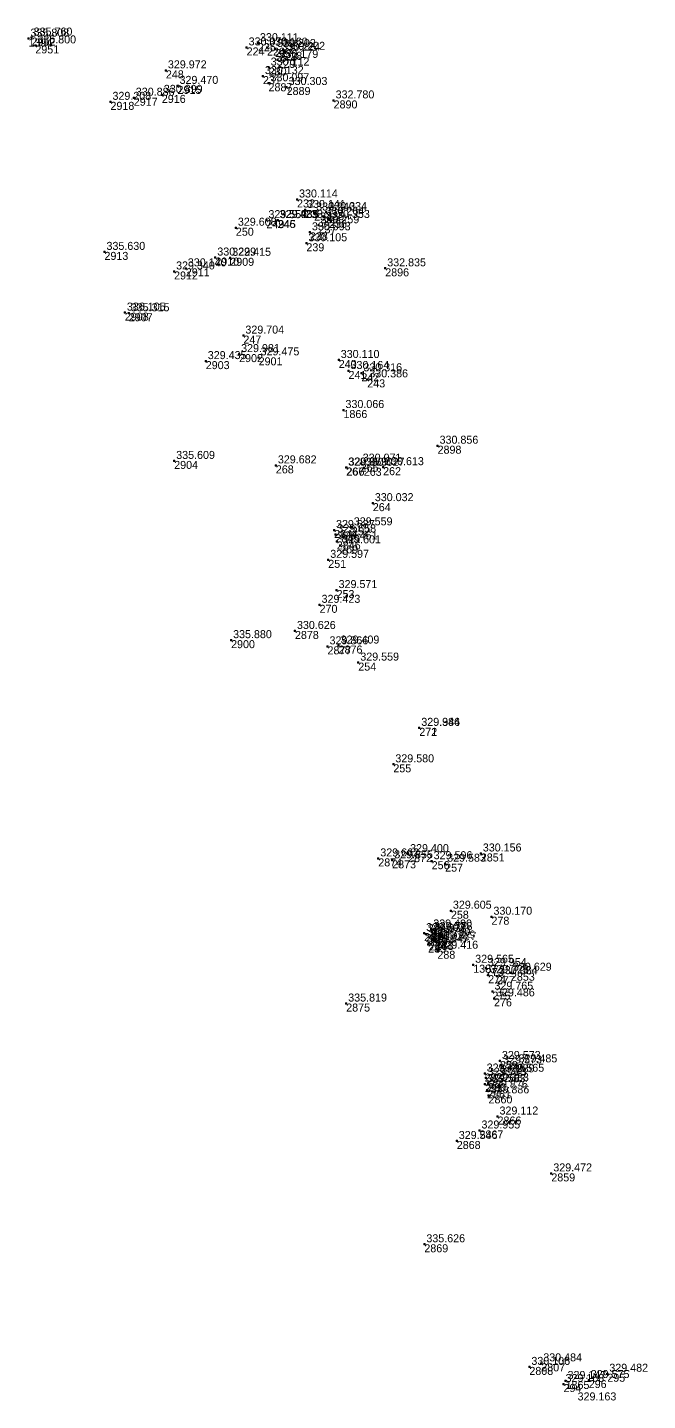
# Model space of a CAD drawing. Extents: x -829398 to -819400, y -1074439 to -1067977.
# Drawn here: x -822787.3 to -822694.5, y -1071096.4 to -1070890.5 of the extents above; entities that cross this region are included whole.
import ezdxf

# ---------------------------------------------------------------- set-up
doc = ezdxf.new("R2010")
doc.units = 0
for name, color, linetype in [('Vrstva 60', 7, 'Continuous'), ('Vrstva 61', 7, 'Continuous'), ('Čísla bodů_doměření_2012', 7, 'Continuous')]:
    doc.layers.add(name, color=color, linetype=linetype)

# ---------------------------------------------------------------- blocks, each defined once
blk = doc.blocks.new('BOD')
at = {"layer": 'Čísla bodů_doměření_2012'}
for p, q in [((-0.15, 0), (0.15, 0)), ((0, -0.15), (0, 0.15))]:
    blk.add_line(p, q, dxfattribs=at)

msp = doc.modelspace()

# ---------------------------------------------------------------- block references
at = {"layer": 'Vrstva 60'}
for p in [(-822787.193, -1070892.156), (-822786.72, -1070892.001), (-822786.165, -1070893.173), (-822752.813, -1070892.84), (-822754.514, -1070893.474), (-822751.46, -1070893.505), (-822750.245, -1070893.708), (-822749.594, -1070894.267), (-822748.866, -1070894.137), (-822766.606, -1070896.916), (-822751.202, -1070896.494), (-822749.889, -1070895.353), (-822764.862, -1070899.241), (-822752.07, -1070897.773), (-822751.234, -1070898.85), (-822771.414, -1070901.018), (-822767.216, -1070900.59), (-822748.517, -1070899.413), (-822741.481, -1070901.421), (-822774.91, -1070901.634), (-822746.959, -1070916.274), (-822745.758, -1070917.843), (-822751.548, -1070919.376), (-822749.879, -1070919.354), (-822749.826, -1070919.357), (-822744.397, -1070918.233), (-822742.979, -1070918.869), (-822742.576, -1070918.166), (-822742.161, -1070919.339), (-822756.124, -1070920.509), (-822745.035, -1070921.196), (-822743.74, -1070920.14), (-822745.557, -1070922.838), (-822775.808, -1070924.132), (-822759.202, -1070924.98), (-822756.96, -1070925.02), (-822765.381, -1070927.065), (-822763.621, -1070926.6), (-822733.747, -1070926.597), (-822772.751, -1070933.233), (-822772.168, -1070933.336), (-822754.997, -1070936.683), (-822760.633, -1070940.507), (-822755.638, -1070939.456), (-822752.715, -1070939.944), (-822740.712, -1070940.338), (-822739.247, -1070941.986), (-822737.323, -1070942.336), (-822736.436, -1070943.248), (-822740.003, -1070947.844), (-822725.905, -1070953.193), (-822765.363, -1070955.474), (-822750.134, -1070956.141), (-822739.603, -1070956.467), (-822739.539, -1070956.468), (-822737.423, -1070955.877), (-822736.965, -1070956.506), (-822734.064, -1070956.41), (-822735.609, -1070961.805), (-822741.421, -1070965.832), (-822741.217, -1070966.486), (-822738.758, -1070965.43), (-822740.999, -1070967.538), (-822740.489, -1070968.134), (-822742.283, -1070970.303), (-822741.033, -1070974.837), (-822743.582, -1070977.048), (-822747.272, -1070980.967), (-822756.839, -1070982.346), (-822742.392, -1070983.277), (-822740.731, -1070983.155), (-822737.784, -1070985.714), (-822728.645, -1070995.491), (-822728.643, -1070995.503), (-822732.532, -1071000.963), (-822730.321, -1071014.431), (-822719.428, -1071014.33), (-822734.788, -1071015.067), (-822732.707, -1071015.355), (-822726.792, -1071015.487), (-822724.771, -1071015.862), (-822723.908, -1071022.91), (-822717.833, -1071023.813), (-822727.922, -1071026.272), (-822727.675, -1071026.427), (-822727.094, -1071026.949), (-822726.85, -1071025.725), (-822726.781, -1071026.1), (-822727.32, -1071027.979), (-822727.221, -1071027.675), (-822726.327, -1071027.38), (-822726.196, -1071027.586), (-822725.933, -1071028.911), (-822720.57, -1071031.015), (-822718.657, -1071031.513), (-822718.324, -1071032.581), (-822717.021, -1071032.727), (-822714.914, -1071032.21), (-822717.686, -1071035.047), (-822739.592, -1071036.83), (-822717.449, -1071036.049), (-822716.567, -1071045.441), (-822718.85, -1071047.324), (-822716.381, -1071046.107), (-822716.032, -1071047.356), (-822714.071, -1071045.95), (-822718.819, -1071048.912), (-822718.665, -1071047.946), (-822718.334, -1071048.77), (-822718.491, -1071049.827), (-822718.272, -1071050.598), (-822716.924, -1071053.77), (-822723.03, -1071057.437), (-822719.631, -1071055.863), (-822708.868, -1071062.296), (-822727.886, -1071072.923), (-822710.368, -1071090.775), (-822712.153, -1071091.309), (-822700.475, -1071092.335), (-822707.035, -1071093.882), (-822706.732, -1071093.418), (-822703.263, -1071093.281)]:
    msp.add_blockref('BOD', p, dxfattribs=at)

# ---------------------------------------------------------------- texts
for s, p in [('1394', (-822787.193, -1070893.356)), ('2952', (-822786.72, -1070893.201)), ('225', (-822752.813, -1070894.04)), ('2951', (-822786.165, -1070894.373)), ('224', (-822754.514, -1070894.674)), ('226', (-822751.46, -1070894.705)), ('227', (-822750.245, -1070894.908)), ('223', (-822749.594, -1070895.467)), ('228', (-822748.866, -1070895.337)), ('248', (-822766.606, -1070898.116)), ('230', (-822751.202, -1070897.694)), ('229', (-822749.889, -1070896.553)), ('2915', (-822764.862, -1070900.441)), ('231', (-822752.07, -1070898.973)), ('2887', (-822751.234, -1070900.05)), ('2917', (-822771.414, -1070902.218)), ('2916', (-822767.216, -1070901.79)), ('2889', (-822748.517, -1070900.613)), ('2918', (-822774.91, -1070902.834)), ('2890', (-822741.481, -1070902.621)), ('232', (-822746.959, -1070917.474)), ('249', (-822751.548, -1070920.576)), ('246', (-822749.879, -1070920.554)), ('245', (-822749.826, -1070920.557)), ('233', (-822745.758, -1070919.043)), ('234', (-822744.397, -1070919.433)), ('244', (-822742.979, -1070920.069)), ('235', (-822742.576, -1070919.366)), ('236', (-822742.161, -1070920.539)), ('250', (-822756.124, -1070921.709)), ('238', (-822745.035, -1070922.396)), ('237', (-822743.74, -1070921.34)), ('239', (-822745.557, -1070924.038)), ('2913', (-822775.808, -1070925.332)), ('2910', (-822759.202, -1070926.18)), ('2909', (-822756.96, -1070926.22)), ('2912', (-822765.381, -1070928.265)), ('2911', (-822763.621, -1070927.8)), ('2896', (-822733.747, -1070927.797)), ('2908', (-822772.751, -1070934.433)), ('2907', (-822772.168, -1070934.536)), ('247', (-822754.997, -1070937.883)), ('2902', (-822755.638, -1070940.656)), ('2901', (-822752.715, -1070941.144)), ('240', (-822740.712, -1070941.538)), ('2903', (-822760.633, -1070941.707)), ('241', (-822739.247, -1070943.186)), ('242', (-822737.323, -1070943.536)), ('243', (-822736.436, -1070944.448)), ('1866', (-822740.003, -1070949.044)), ('2898', (-822725.905, -1070954.393)), ('2904', (-822765.363, -1070956.674)), ('268', (-822750.134, -1070957.341)), ('267', (-822739.603, -1070957.667)), ('266', (-822739.539, -1070957.668)), ('265', (-822737.423, -1070957.077)), ('263', (-822736.965, -1070957.706)), ('262', (-822734.064, -1070957.61)), ('264', (-822735.609, -1070963.005)), ('2844', (-822741.421, -1070967.032)), ('2845', (-822741.217, -1070967.686)), ('252', (-822738.758, -1070966.63)), ('2846', (-822740.999, -1070968.738)), ('269', (-822740.489, -1070969.334)), ('251', (-822742.283, -1070971.503)), ('253', (-822741.033, -1070976.037)), ('270', (-822743.582, -1070978.248)), ('2878', (-822747.272, -1070982.167)), ('2900', (-822756.839, -1070983.546)), ('2877', (-822742.392, -1070984.477)), ('2876', (-822740.731, -1070984.355)), ('254', (-822737.784, -1070986.914)), ('271', (-822728.645, -1070996.691)), ('272', (-822728.643, -1070996.703)), ('255', (-822732.532, -1071002.163)), ('2872', (-822730.321, -1071015.631)), ('2851', (-822719.428, -1071015.53)), ('2874', (-822734.788, -1071016.267)), ('2873', (-822732.707, -1071016.555)), ('256', (-822726.792, -1071016.687)), ('257', (-822724.771, -1071017.062)), ('258', (-822723.908, -1071024.11)), ('278', (-822717.833, -1071025.013)), ('287', (-822727.922, -1071027.472)), ('286', (-822727.675, -1071027.627)), ('281', (-822726.85, -1071026.925)), ('280', (-822726.781, -1071027.3)), ('285', (-822727.32, -1071029.179)), ('284', (-822727.221, -1071028.875)), ('279', (-822727.094, -1071028.149)), ('282', (-822726.327, -1071028.58)), ('283', (-822726.196, -1071028.786)), ('288', (-822725.933, -1071030.111)), ('1387', (-822720.57, -1071032.215)), ('273', (-822718.657, -1071032.713)), ('274', (-822718.324, -1071033.781)), ('277', (-822717.021, -1071033.927)), ('2853', (-822714.914, -1071033.41)), ('275', (-822717.686, -1071036.247)), ('2875', (-822739.592, -1071038.03)), ('276', (-822717.449, -1071037.249)), ('293', (-822718.85, -1071048.524)), ('259', (-822716.567, -1071046.641)), ('260', (-822716.381, -1071047.307)), ('261', (-822716.032, -1071048.556)), ('289', (-822714.071, -1071047.15)), ('291', (-822718.819, -1071050.112)), ('292', (-822718.665, -1071049.146)), ('290', (-822718.334, -1071049.97)), ('2861', (-822718.491, -1071051.027)), ('2860', (-822718.272, -1071051.798)), ('2866', (-822716.924, -1071054.97)), ('2868', (-822723.03, -1071058.637)), ('2867', (-822719.631, -1071057.063)), ('2859', (-822708.868, -1071063.496)), ('2869', (-822727.886, -1071074.123)), ('2808', (-822712.153, -1071092.509)), ('2807', (-822710.368, -1071091.975)), ('295', (-822700.475, -1071093.535)), ('294', (-822707.035, -1071095.082)), ('1865', (-822706.732, -1071094.618)), ('296', (-822703.263, -1071094.481))]:
    msp.add_text(s, height=1.2, dxfattribs=at).set_placement(p)
at = {"layer": 'Vrstva 61'}
for s, p in [('335.808', (-822786.893, -1070891.856)), ('335.760', (-822786.42, -1070891.701)), ('335.800', (-822785.865, -1070892.873)), ('330.070', (-822754.214, -1070893.174)), ('330.111', (-822752.513, -1070892.54)), ('330.160', (-822751.16, -1070893.205)), ('330.202', (-822749.945, -1070893.408)), ('330.224', (-822749.294, -1070893.967)), ('330.202', (-822748.566, -1070893.837)), ('330.112', (-822750.902, -1070896.194)), ('330.179', (-822749.589, -1070895.053)), ('329.972', (-822766.306, -1070896.616)), ('330.132', (-822751.77, -1070897.473)), ('330.899', (-822766.916, -1070900.29)), ('329.470', (-822764.562, -1070898.941)), ('330.097', (-822750.934, -1070898.55)), ('330.303', (-822748.217, -1070899.113)), ('329.208', (-822774.61, -1070901.334)), ('330.886', (-822771.114, -1070900.718)), ('332.780', (-822741.181, -1070901.121)), ('330.114', (-822746.659, -1070915.974)), ('330.141', (-822745.458, -1070917.543)), ('330.240', (-822744.097, -1070917.933)), ('330.264', (-822742.679, -1070918.569)), ('330.334', (-822742.276, -1070917.866)), ('329.608', (-822755.824, -1070920.209)), ('329.551', (-822751.248, -1070919.076)), ('329.489', (-822749.579, -1070919.054)), ('329.935', (-822749.526, -1070919.057)), ('330.093', (-822744.735, -1070920.896)), ('330.259', (-822743.44, -1070919.84)), ('330.353', (-822741.861, -1070919.039)), ('330.105', (-822745.257, -1070922.538)), ('335.630', (-822775.508, -1070923.832)), ('330.229', (-822758.902, -1070924.68)), ('329.415', (-822756.66, -1070924.72)), ('329.340', (-822765.081, -1070926.765)), ('330.140', (-822763.321, -1070926.3)), ('332.835', (-822733.447, -1070926.297)), ('336.105', (-822772.451, -1070932.933)), ('335.315', (-822771.868, -1070933.036)), ('329.704', (-822754.697, -1070936.383)), ('329.981', (-822755.338, -1070939.156)), ('329.435', (-822760.333, -1070940.207)), ('329.475', (-822752.415, -1070939.644)), ('330.110', (-822740.412, -1070940.038)), ('330.164', (-822738.947, -1070941.686)), ('330.316', (-822737.023, -1070942.036)), ('330.386', (-822736.136, -1070942.948)), ('330.066', (-822739.703, -1070947.544)), ('330.856', (-822725.605, -1070952.893)), ('335.609', (-822765.063, -1070955.174)), ('329.682', (-822749.834, -1070955.841)), ('330.071', (-822737.123, -1070955.577)), ('329.379', (-822739.303, -1070956.167)), ('329.953', (-822739.239, -1070956.168)), ('330.027', (-822736.665, -1070956.206)), ('330.613', (-822733.764, -1070956.11)), ('330.032', (-822735.309, -1070961.505)), ('329.687', (-822741.121, -1070965.532)), ('329.658', (-822740.917, -1070966.186)), ('329.559', (-822738.458, -1070965.13)), ('329.461', (-822740.699, -1070967.238)), ('329.601', (-822740.189, -1070967.834)), ('329.597', (-822741.983, -1070970.003)), ('329.571', (-822740.733, -1070974.537)), ('329.423', (-822743.282, -1070976.748)), ('330.626', (-822746.972, -1070980.667)), ('335.880', (-822756.539, -1070982.046)), ('329.866', (-822742.092, -1070982.977)), ('329.409', (-822740.431, -1070982.855)), ('329.559', (-822737.484, -1070985.414)), ('329.946', (-822728.345, -1070995.191)), ('329.384', (-822728.343, -1070995.203)), ('329.580', (-822732.232, -1071000.663)), ('329.662', (-822734.488, -1071014.767)), ('329.855', (-822732.407, -1071015.055)), ('329.400', (-822730.021, -1071014.131)), ('329.596', (-822726.492, -1071015.187)), ('329.583', (-822724.471, -1071015.562)), ('330.156', (-822719.128, -1071014.03)), ('329.605', (-822723.608, -1071022.61)), ('330.170', (-822717.533, -1071023.513)), ('329.603', (-822727.622, -1071025.972)), ('329.490', (-822726.55, -1071025.425)), ('329.778', (-822726.481, -1071025.8)), ('329.938', (-822727.375, -1071026.127)), ('329.647', (-822727.02, -1071027.679)), ('329.936', (-822726.921, -1071027.375)), ('329.790', (-822726.794, -1071026.649)), ('329.759', (-822726.027, -1071027.08)), ('329.547', (-822725.896, -1071027.286)), ('329.416', (-822725.633, -1071028.611)), ('329.565', (-822720.27, -1071030.715)), ('329.954', (-822718.357, -1071031.213)), ('330.629', (-822714.614, -1071031.91)), ('329.723', (-822718.024, -1071032.281)), ('330.084', (-822716.721, -1071032.427)), ('329.765', (-822717.386, -1071034.747)), ('329.486', (-822717.149, -1071035.749)), ('335.819', (-822739.292, -1071036.53)), ('329.573', (-822716.267, -1071045.141)), ('329.573', (-822716.081, -1071045.807)), ('329.485', (-822713.771, -1071045.65)), ('329.716', (-822718.55, -1071047.024)), ('329.583', (-822718.519, -1071048.612)), ('329.713', (-822718.365, -1071047.646)), ('329.333', (-822718.034, -1071048.47)), ('329.565', (-822715.732, -1071047.056)), ('329.876', (-822718.191, -1071049.527)), ('329.886', (-822717.972, -1071050.298)), ('329.112', (-822716.624, -1071053.47)), ('329.955', (-822719.331, -1071055.563)), ('329.546', (-822722.73, -1071057.137)), ('329.472', (-822708.568, -1071061.996)), ('335.626', (-822727.586, -1071072.623)), ('330.106', (-822711.853, -1071091.009)), ('330.484', (-822710.068, -1071090.475)), ('329.168', (-822706.735, -1071093.582)), ('329.147', (-822706.432, -1071093.118)), ('329.575', (-822702.963, -1071092.981)), ('329.482', (-822700.175, -1071092.035)), ('329.163', (-822704.931, -1071096.335))]:
    msp.add_text(s, height=1.2, dxfattribs=at).set_placement(p)

doc.saveas('drawing.dxf')
